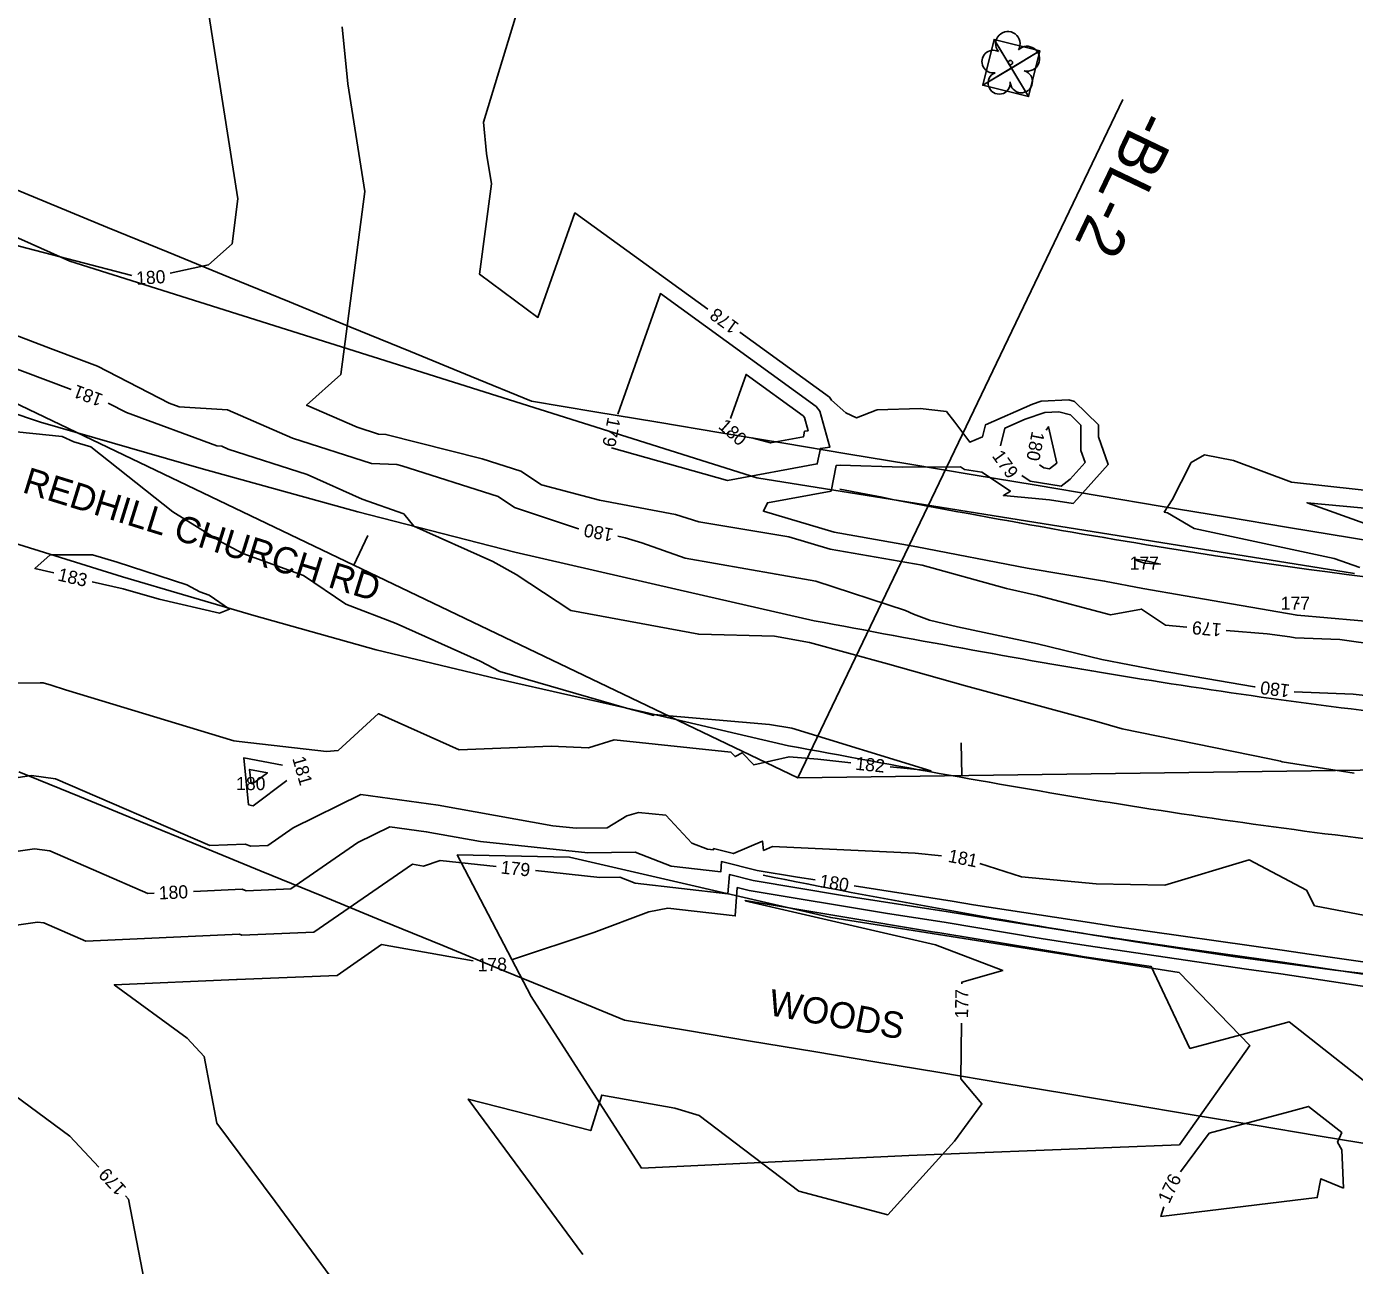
# Model space of a CAD drawing. Extents: x 2086416 to 2115205, y 575507 to 632762.
# Drawn here: x 2110857.5 to 2111059.8, y 581552.3 to 581741 of the extents above; entities that cross this region are included whole.
import ezdxf

# ---------------------------------------------------------------- set-up
doc = ezdxf.new("R2010")
doc.units = 0
for name, color, linetype in [('CTL Bench Mark CELL', 7, 'Continuous'), ('Default', 7, 'Continuous'), ('DTM Contours Major', 7, 'Continuous'), ('DTM Contours Major Text', 7, 'Continuous'), ('DTM Contours Minor', 7, 'Continuous'), ('DTM Contours Minor Text', 7, 'Continuous'), ('Exist Hydrographic FEMA Cross Section', 7, 'Continuous'), ('Exist Right of Way Line', 7, 'Continuous'), ('Exist Roads EOP', 7, 'Continuous'), ('Exist Roads EOP Text', 7, 'Continuous'), ('Exist Vegetation Tree CELL', 7, 'Continuous'), ('Exist Vegetation Woods Line', 7, 'Continuous'), ('Exist Vegetation Woods Line Text', 7, 'Continuous')]:
    doc.layers.add(name, color=color, linetype=linetype)

msp = doc.modelspace()

# ---------------------------------------------------------------- linework, layer by layer
at = {"layer": 'CTL Bench Mark CELL'}
msp.add_line((2111007.5, 581734.68), (2111007.5, 581734.68), dxfattribs=at)
msp.add_lwpolyline([(2111004.87, 581739.03), (2111011.85, 581737.3), (2111010.12, 581730.33), (2111003.15, 581732.05)], close=True, dxfattribs=at)
for points in [[(2111011.85, 581737.3), (2111003.15, 581732.05), (2111007.5, 581734.68), (2111010.12, 581730.33), (2111004.87, 581739.03)], [(2111007.5, 581734.68), (2111011.85, 581737.3), (2111004.87, 581739.03), (2111007.5, 581734.68)], [(2111007.5, 581734.68), (2111003.15, 581732.05), (2111010.12, 581730.33), (2111007.5, 581734.68)]]:
    msp.add_lwpolyline(points, dxfattribs=at)
at = {"layer": 'Default'}
for p, q in [((2110456.37, 581874.95), (2110974.98, 581626.56)), ((2110974.98, 581626.56), (2111024.48, 581729.91)), ((2110907.32, 581658.96), (2110909.48, 581663.47)), ((2110974.98, 581626.56), (2111508.23, 581633.8)), ((2110999.95, 581626.89), (2110999.88, 581631.89))]:
    msp.add_line(p, q, dxfattribs=at)
at = {"layer": 'DTM Contours Major'}
for points in [[(2110857.81, 581782.51), (2110864.26, 581780.86), (2110867.35, 581778.23), (2110871.08, 581774.64), (2110881.14, 581768.63), (2110883.33, 581762.7), (2110885.27, 581742.86), (2110889.69, 581714.76), (2110888.79, 581707.91), (2110885.2, 581704.69), (2110879.38, 581703.43)], [(2110873.53, 581703.08), (2110856.38, 581707.56), (2110842.13, 581711.99), (2110834.59, 581705.91), (2110820.11, 581710.34), (2110817.82, 581710.24), (2110811.38, 581712.14), (2110818.2, 581708.5), (2110833.97, 581702.31), (2110837.45, 581701), (2110842.24, 581699.17)], [(2110847.85, 581697.03), (2110861.11, 581691.96), (2110865.83, 581690.2), (2110868.29, 581689.26), (2110879.23, 581683.6), (2110880.71, 581683.05), (2110888.09, 581682.6), (2110898.02, 581678.3), (2110910.04, 581674.42), (2110913.9, 581674.27), (2110914.63, 581674.08), (2110929.32, 581669.43), (2110931.83, 581667.74), (2110941.39, 581664.51), (2110941.63, 581664.47)], [(2110975.78, 581681.69), (2110967.08, 581688), (2110964.7, 581681.27)], [(2110967.99, 581678.36), (2110970.82, 581677.57), (2110975.83, 581678.48), (2110976.01, 581679.35), (2110976.54, 581679.42), (2110975.97, 581681.44), (2110975.78, 581681.69)], [(2111013.31, 581673.63), (2111014.41, 581674.5), (2111013.16, 581680.03), (2111012.82, 581679.52)], [(2111011.78, 581674.22), (2111012.46, 581673.76), (2111013.31, 581673.63)], [(2110947.53, 581663.35), (2110948.69, 581663.13), (2110951.2, 581662.35), (2110957.79, 581660.03), (2110971.67, 581657.55), (2110977.7, 581656.52), (2110991.39, 581652.02), (2110992.6, 581651.48), (2110995.02, 581650.56), (2110999.28, 581649.57), (2111011.46, 581646.94), (2111021.3, 581644.58), (2111029.72, 581642.96), (2111044.53, 581640.43), (2111044.64, 581640.42)], [(2111050.59, 581639.65), (2111059.56, 581639.3), (2111074.86, 581637.63), (2111092.6, 581635.13), (2111097.3, 581633.95), (2111099.33, 581633.73), (2111122.83, 581631.48), (2111123.23, 581631.44), (2111147.14, 581630.22), (2111147.88, 581630.21), (2111150.02, 581630.22)], [(2110876.9, 581608.98), (2110875.97, 581608.94), (2110861.02, 581615.41), (2110858.67, 581615.72), (2110842.9, 581613.47), (2110829.57, 581614.6), (2110813.49, 581617.62), (2110802.61, 581621.03), (2110784.33, 581624.43), (2110784.33, 581629.17)], [(2110891.68, 581625.67), (2110891.47, 581627.83), (2110894.17, 581627.32), (2110891.91, 581625.62), (2110891.68, 581625.67)], [(2110977.61, 581610.99), (2110974.93, 581611.41), (2110968.79, 581612.43), (2110963.33, 581613.78), (2110963.22, 581612.21), (2110955.69, 581613.08), (2110950.2, 581615.22), (2110942.99, 581615.11), (2110926.63, 581616.85), (2110918.38, 581618.34), (2110912.82, 581619.09), (2110907.96, 581616.69), (2110897.75, 581609.63), (2110890.96, 581609.35), (2110890.33, 581609.58), (2110882.9, 581609.25)], [(2111082.5, 581595.71), (2111075.86, 581596.43), (2111069.63, 581597.3), (2111052.87, 581599.68), (2111049.12, 581600.24), (2111023.26, 581603.91), (2111019.43, 581604.48), (2111001.74, 581607.21), (2110998.51, 581607.75), (2110983.54, 581610.07)]]:
    msp.add_lwpolyline(points, dxfattribs=at)
at = {"layer": 'DTM Contours Minor'}
for points in [[(2110961.28, 581697.94), (2110941.02, 581712.61), (2110935.39, 581696.68), (2110926.5, 581703.26), (2110928.29, 581717.02), (2110927.56, 581721.64), (2110927.09, 581726.43), (2110938.5, 581764.02), (2110958.94, 581787.46), (2110972.43, 581820.41), (2110963.81, 581829.93), (2110966.47, 581833.96)], [(2110905.56, 581740.96), (2110906.42, 581732.25), (2110908.99, 581715.89), (2110905.35, 581687.97), (2110900.14, 581683.3), (2110907.85, 581679.96), (2110911.1, 581678.91), (2110912.22, 581678.87), (2110926.91, 581675.14), (2110932.8, 581673.28), (2110935.94, 581671.16), (2110944.78, 581668.87), (2110956.33, 581666.68), (2110959.91, 581665.57), (2110973.62, 581663.25), (2110979.88, 581661.39), (2110993.91, 581658.93), (2111006.74, 581655.37), (2111011.49, 581654.3), (2111022.59, 581651.38), (2111027.31, 581652.26), (2111030.98, 581649.79), (2111034.24, 581649.51)], [(2110977.78, 581683.12), (2110954.05, 581700.31), (2110947.57, 581681.97)], [(2111033.98, 581654.26), (2111027.52, 581655.4), (2111021.7, 581656.52), (2111009.92, 581658.49), (2110993.12, 581661.76), (2110980.51, 581663.98), (2110969.74, 581667.17), (2110970.33, 581668.46), (2110980.03, 581670.23), (2110980.81, 581674.12), (2110981.43, 581674.2), (2110990.94, 581673.89), (2110999.77, 581673.93), (2111000.38, 581673.54), (2111003, 581673.11), (2111007.37, 581670.24), (2111006.29, 581669.55), (2111013.29, 581668.91), (2111016.9, 581668.36), (2111017.03, 581668.46), (2111022.26, 581674.27), (2111020.76, 581678.49), (2111020.77, 581680.3), (2111017.11, 581683.9), (2111016.28, 581684.11), (2111012.05, 581683.93), (2111010.72, 581683.48), (2111003.55, 581680.3), (2111003.09, 581678.48), (2111001.19, 581677.68), (2110998.91, 581680.74), (2110997.6, 581682.37), (2110993.61, 581682.82), (2110987.06, 581682.61), (2110986.89, 581682.55), (2110983.89, 581681.37), (2110982.3, 581682.15), (2110980.12, 581684.1), (2110979.79, 581684.54), (2110966.14, 581694.42)], [(2110849.4, 581691.27), (2110864.3, 581685.71)], [(2110869.92, 581683.61), (2110870.01, 581683.58), (2110872.69, 581682.19), (2110886.48, 581677.11), (2110887.21, 581677.07), (2110888.2, 581676.64), (2110900.23, 581672.75), (2110908.61, 581668.98), (2110914.95, 581666.77), (2110916.46, 581664.89), (2110928.52, 581659.48), (2110932.08, 581657.5), (2110940.41, 581652.05), (2110959.88, 581648.42), (2110971.42, 581648.11), (2110976.77, 581647.17), (2110988.63, 581643.91), (2111000.53, 581640.56), (2111020.53, 581635.11), (2111024.4, 581634.03), (2111046.82, 581629.45), (2111048.5, 581629.07), (2111048.77, 581629), (2111059.73, 581627.25)], [(2110946.57, 581676.83), (2110964.27, 581671.86), (2110977.93, 581674.36), (2110978.41, 581676.74), (2110979.85, 581676.92), (2110978.32, 581682.42), (2110977.78, 581683.12)], [(2111018.07, 581676.4), (2111018.1, 581680.27), (2111016.5, 581681.84), (2111014.71, 581682.29), (2111012.62, 581682.2), (2111009.6, 581681.2), (2111006.53, 581679.83), (2111005.84, 581677.12)], [(2110842.52, 581680.61), (2110862.89, 581678.56), (2110864.67, 581677.73), (2110867.29, 581676.98), (2110879.75, 581667.09), (2110887.27, 581662.38), (2110890.41, 581660.71), (2110899.69, 581657.39), (2110906.1, 581653), (2110913.79, 581650.08), (2110926.59, 581644.34), (2110929.58, 581642.73), (2110948.86, 581637.16), (2110951.39, 581636.51), (2110953.03, 581636.04), (2110953.05, 581636.21), (2110970.66, 581634.65), (2110974.07, 581634.09), (2110995.24, 581627.6), (2110989.03, 581628.23)], [(2111009.08, 581672.6), (2111010.38, 581671.72), (2111015.11, 581671), (2111016.46, 581672.07), (2111018.72, 581674.58), (2111018.07, 581676.4)], [(2111076.02, 581668.76), (2111050.2, 581671.6), (2111041.35, 581674.9), (2111036.91, 581675.75), (2111034.88, 581674.58), (2111033.37, 581671.6), (2111032.02, 581668.91), (2111030.8, 581667.04), (2111031.29, 581666.94), (2111035.33, 581664.54), (2111056.7, 581659.98), (2111060.58, 581658.59)], [(2111070.83, 581661.91), (2111052.56, 581668.44), (2111077.82, 581666.09), (2111082.45, 581665.57)], [(2110885.29, 581654.39), (2110883.87, 581654.9), (2110881.88, 581655.95), (2110871.29, 581659.4), (2110867.53, 581660.53), (2110861.07, 581660.53), (2110858.75, 581658.42), (2110861.64, 581657.76)], [(2111027.79, 581659.26), (2111026.7, 581659.61), (2111026.31, 581659.85), (2111027.78, 581659.67), (2111027.84, 581659.66), (2111030.19, 581659.12), (2111027.79, 581659.26)], [(2110867.49, 581656.41), (2110872.18, 581655.33), (2110877.68, 581653.75), (2110886.89, 581651.63), (2110888.4, 581652.26), (2110885.29, 581654.39)], [(2111168.17, 581645.41), (2111168.97, 581645.31), (2111172.74, 581644.84), (2111194.02, 581644.23), (2111176.11, 581643.9), (2111172.57, 581643.81), (2111158.61, 581644.07), (2111154.65, 581644.18), (2111135.04, 581644.56), (2111124.61, 581644.89), (2111115.46, 581645.42), (2111106.17, 581646.37), (2111094.09, 581647.15), (2111076.28, 581648.94), (2111064.89, 581650.09), (2111051.02, 581651.31), (2111033.98, 581654.26)], [(2111050.81, 581653.14), (2111051.17, 581653.11), (2111051.34, 581653.08), (2111051.31, 581653.07), (2111051.18, 581653.08), (2111051.14, 581653.08), (2111050.81, 581653.14)], [(2111040.21, 581649), (2111046.47, 581648.46), (2111049.91, 581648.03), (2111050.75, 581647.88), (2111057.54, 581647.61), (2111075.81, 581645.03), (2111083.62, 581643.07), (2111103.56, 581640.9), (2111112.25, 581640.07), (2111123.96, 581638.8), (2111133.06, 581638.34), (2111152.19, 581638), (2111160.29, 581638.04), (2111171.77, 581637.82), (2111172.14, 581637.73), (2111178.61, 581637.94), (2111201.19, 581638.98), (2111205.15, 581639.2), (2111206.66, 581639.57), (2111221.28, 581640.1), (2111223.41, 581640.06), (2111239.38, 581640.48)], [(2110983.07, 581628.85), (2110978, 581629.37), (2110973.65, 581629.75), (2110968.25, 581628.5), (2110966.51, 581630.36), (2110965.42, 581629.78), (2110964.79, 581630.46), (2110947.02, 581632.32), (2110943.07, 581631.1), (2110937.41, 581631.35), (2110923.38, 581630.81), (2110911.16, 581636.31), (2110911.1, 581636.32), (2110904.94, 581630.73), (2110903.18, 581630.56), (2110889.88, 581632.09), (2110889.08, 581632.18), (2110863.41, 581639.97), (2110861.22, 581640.65), (2110861.21, 581640.65), (2110860.03, 581641), (2110859.55, 581641.04), (2110830.03, 581640.99)], [(2110929.04, 581613.04), (2110920.49, 581613.95), (2110917.95, 581613.11), (2110916.27, 581613.41), (2110901.27, 581603.04), (2110890.27, 581602.57), (2110889.9, 581602.71), (2110866.52, 581601.67), (2110860.13, 581604.43), (2110859.13, 581604.56), (2110830.62, 581600.5), (2110829.64, 581600.58), (2110804.08, 581605.37), (2110803.32, 581605.61), (2110774.57, 581610.97), (2110774.57, 581632.28), (2110758.83, 581634.4), (2110756.92, 581632.1)], [(2110891.27, 581622.44), (2110890.57, 581629.59), (2110896.48, 581628.48)], [(2110753.08, 581627.49), (2110744.05, 581616.65), (2110743.92, 581616.36), (2110723.28, 581627.9), (2110743.8, 581615.32), (2110744.35, 581615.09), (2110773.2, 581609.58), (2110773.78, 581609.34), (2110774.18, 581609.1), (2110802.91, 581603.58), (2110803.77, 581602.94), (2110829.06, 581598.07), (2110829.72, 581597.73), (2110848.6, 581586.56), (2110853.13, 581580), (2110864.1, 581571.94), (2110868.48, 581567.23)], [(2110996.86, 581614.66), (2110992.83, 581615.07), (2110971.13, 581616.07), (2110969.76, 581615.48), (2110969.59, 581616.9), (2110965.17, 581615), (2110962.13, 581615.76), (2110962.11, 581615.56), (2110961.19, 581615.67), (2110958.82, 581616.6), (2110954.89, 581620.84), (2110950.68, 581621.28), (2110948.91, 581620.73), (2110945.91, 581618.94), (2110941.19, 581618.86), (2110937.67, 581619.24), (2110920.18, 581622.39), (2110908.4, 581623.98), (2110898.09, 581618.9), (2110894.23, 581616.23), (2110891.66, 581616.12), (2110890.77, 581616.45), (2110885.42, 581616.21), (2110861.9, 581626.39), (2110858.22, 581626.88), (2110855.17, 581626.45)], [(2110897.15, 581626.15), (2110892.02, 581622.27), (2110891.27, 581622.44)], [(2111196.72, 581603.77), (2111172.9, 581599.04), (2111171.11, 581598.89), (2111169.44, 581598.86), (2111145.84, 581603.49), (2111139.11, 581602.96), (2111128.42, 581602.29), (2111121.08, 581599.17), (2111117.24, 581599.62), (2111101.55, 581602.41), (2111089.76, 581603.22), (2111073.51, 581605.15), (2111070.03, 581604.02), (2111065.65, 581604.74), (2111053.68, 581607.05), (2111052.47, 581609.42), (2111043.72, 581614.04), (2111030.87, 581610.21), (2111020.41, 581610.41), (2111009.04, 581611.48), (2111002.71, 581613.49)], [(2111130.22, 581588.38), (2111121.05, 581588.76), (2111106.61, 581590.81), (2111099.14, 581591.63), (2111088.39, 581592.8), (2111069.38, 581595.44), (2111061.09, 581596.62), (2111048.83, 581598.45), (2111033.29, 581600.66), (2111019.16, 581602.75), (2111006.9, 581604.64), (2110997.88, 581606.14), (2110981.78, 581608.64), (2110968.18, 581610.9), (2110964.54, 581611.8), (2110964.32, 581608.85), (2110950.19, 581610.5), (2110947.86, 581611.4), (2110944.79, 581611.36), (2110935.01, 581612.4)], [(2111089.4, 581555.52), (2111077.55, 581561.12), (2111076.79, 581568.08), (2111074.63, 581570.74), (2111076.73, 581572.4), (2111068.24, 581581.12), (2111061.92, 581586.55), (2111068.35, 581593.7), (2111048.53, 581596.67), (2111043.32, 581597.41), (2111018.89, 581601.02), (2111012.06, 581602.08), (2110997.25, 581604.54), (2110988.64, 581605.87), (2110967.58, 581609.38), (2110965.75, 581609.83), (2110965.43, 581605.5), (2110955.18, 581606.69), (2110952.29, 581606.13), (2110943.89, 581602.96), (2110931.34, 581598.81)], [(2111061.52, 581539.99), (2111063.18, 581540.25), (2111064.17, 581540.37), (2111066.23, 581550.97), (2111066.29, 581550.94), (2111065.54, 581568.97), (2111063.51, 581572.55), (2111065.42, 581577.09), (2111049.84, 581589.37), (2111048.92, 581589.13), (2111034.71, 581585.33), (2111028.8, 581597.79), (2111018.62, 581599.29), (2111017.22, 581599.51), (2110996.62, 581602.93), (2110995.49, 581603.1), (2110966.97, 581607.85), (2110966.96, 581607.85), (2110966.96, 581607.82), (2110967.56, 581607.66), (2110995.97, 581601.12), (2111006.18, 581597.21), (2110999.98, 581595.42), (2110999.97, 581595.17)], [(2110925.52, 581598.64), (2110911.57, 581601.13), (2110904.79, 581596.44), (2110889.57, 581595.8), (2110889.46, 581595.84), (2110870.84, 581595.01), (2110881.93, 581586.86), (2110884.54, 581584.07), (2110886.49, 581573.95), (2110895.38, 581561.98), (2110911.97, 581539.46)], [(2110999.9, 581589.17), (2110999.8, 581580.68), (2111003.02, 581576.87), (2110998.83, 581571.21), (2110988.66, 581559.99), (2110975.14, 581563.57), (2110959.96, 581575.11), (2110956.22, 581576.23), (2110945.1, 581578.22), (2110943.43, 581572.79), (2110924.77, 581577.6), (2110942.21, 581553.94)], [(2111058.1, 581564.04), (2111057.86, 581569.87), (2111057.2, 581571.02), (2111057.82, 581572.49), (2111052.78, 581576.47), (2111049.99, 581575.72), (2111037.65, 581572.42), (2111033.27, 581566.52)], [(2111030.73, 581561.17), (2111030.28, 581559.69), (2111054.1, 581562.6), (2111054.65, 581565.45), (2111058.1, 581564.04)], [(2110872.57, 581562.84), (2110873.01, 581562.37), (2110879.72, 581527.7), (2110880.43, 581526.75), (2110881.74, 581524.97)]]:
    msp.add_lwpolyline(points, dxfattribs=at)
at = {"layer": 'Exist Hydrographic FEMA Cross Section'}
for points in [[(2111068.93, 581661.5), (2111059.32, 581663.1), (2111049.71, 581664.7), (2111040.1, 581666.3), (2111030.49, 581667.9), (2111020.89, 581669.5), (2111011.28, 581671.11), (2111001.67, 581672.71), (2110992.06, 581674.31), (2110982.45, 581675.91), (2110972.85, 581677.51), (2110963.24, 581679.11), (2110953.63, 581680.71), (2110944.03, 581682.32), (2110934.42, 581683.91), (2110925.19, 581687.7), (2110915.97, 581691.48), (2110906.74, 581695.27), (2110897.52, 581699.06), (2110888.29, 581702.84), (2110879.07, 581706.62), (2110869.84, 581710.41), (2110860.61, 581714.19), (2110851.39, 581717.98)], [(2111063.86, 581570.42), (2111054.26, 581572.02), (2111044.65, 581573.62), (2111035.04, 581575.22), (2111025.43, 581576.83), (2111015.82, 581578.43), (2111006.21, 581580.02), (2110996.6, 581581.63), (2110987, 581583.23), (2110977.39, 581584.83), (2110967.78, 581586.43), (2110958.18, 581588.03), (2110948.57, 581589.63), (2110939.34, 581593.42), (2110930.11, 581597.2), (2110920.89, 581600.99), (2110911.67, 581604.77), (2110902.44, 581608.56), (2110893.22, 581612.34), (2110883.99, 581616.13), (2110874.77, 581619.91), (2110865.54, 581623.7), (2110856.32, 581627.48)]]:
    msp.add_lwpolyline(points, dxfattribs=at)
at = {"layer": 'Exist Right of Way Line'}
for centre, radius, start, end in [((2111262.84, 583087.65), 1444.79, 258.76631, 260.84314), ((2111174.98, 582542.55), 892.65, 260.84314, 266.74835), ((2111262.84, 583087.65), 1504.79, 258.76631, 260.84314), ((2111174.98, 582542.55), 952.65, 260.84314, 266.74835)]:
    msp.add_arc(centre, radius, start, end, dxfattribs=at)
at = {"layer": 'Exist Roads EOP'}
for points in [[(2110859.62, 581680.71), (2110839.18, 581687.57), (2110822.39, 581693.78), (2110804.41, 581700.49), (2110791.36, 581705.43), (2110777.14, 581711.28), (2110760, 581718.68), (2110741.24, 581726.89), (2110721.85, 581735.85), (2110702.22, 581745.1), (2110680.73, 581755.98), (2110662.27, 581765.85)], [(2110661.71, 581744.29), (2110681.63, 581733.96), (2110708.85, 581721.01), (2110734.15, 581708.98), (2110768.01, 581694.36), (2110797.99, 581682.47), (2110825.02, 581672.22), (2110850.72, 581663.8), (2110872.12, 581657.17), (2110892.09, 581651.25), (2110910.76, 581646.06), (2110929.15, 581641.61), (2110951.61, 581636.54), (2110973.54, 581631.44)], [(2110977.48, 581650.48), (2110956.38, 581655.31), (2110931.86, 581660.94), (2110907.94, 581667.06), (2110884.07, 581673.67), (2110859.62, 581680.71)]]:
    msp.add_lwpolyline(points, dxfattribs=at)
for points in [[(2110977.48, 581650.48), (2111025.79, 581641.84), (2111074.55, 581635.25), (2111123.2, 581631.18), (2111172.22, 581629.18), (2111221.29, 581629.52), (2111270.17, 581631.7), (2111319.13, 581635.84), (2111368.33, 581641.12), (2111417.78, 581647.42)], [(2110973.54, 581631.44), (2111022.55, 581622.76), (2111072.45, 581615.95), (2111122.07, 581611.59), (2111171.98, 581610.01), (2111221.99, 581610.11), (2111271.48, 581612.54), (2111320.96, 581616.67), (2111370.32, 581622.18), (2111419.52, 581628.55)]]:
    msp.add_spline(points, degree=3, dxfattribs=at)
at = {"layer": 'Exist Vegetation Tree CELL'}
msp.add_line((2111007.35, 581735.51), (2111007.35, 581735.51), dxfattribs=at)
msp.add_circle((2111007.35, 581735.51), 0.326, dxfattribs=at)
for centre, radius, start, end in [((2111006.97, 581738.39), 1.86, 330.1651, 219.7134), ((2111004.75, 581735.67), 1.73, 62.6636, 279.3457), ((2111009.9, 581736.1), 1.9, 257.1011, 134.1999), ((2111005.65, 581732.39), 1.69, 111.5671, 6.231), ((2111009.02, 581732.61), 1.7, 181.2822, 74.56)]:
    msp.add_arc(centre, radius, start, end, dxfattribs=at)
at = {"layer": 'Exist Vegetation Woods Line'}
for points in [[(2111059.79, 581657.65), (2110968.73, 581672.25), (2110864.06, 581705.25), (2110784.73, 581740.8), (2110702.3, 581784.67), (2110632.54, 581823.34), (2110568.48, 581865.95), (2110498.27, 581913.79), (2110441.66, 581966.78), (2110387.94, 582016.39), (2110334.43, 582063.69), (2110284.48, 582120.87)], [(2111033.08, 581596.9), (2111043.81, 581585.75), (2111033.1, 581570.65), (2110991.9, 581569.03), (2110951.17, 581567.08), (2110934.36, 581593.21), (2110923.1, 581614.81), (2110940.19, 581614.48)], [(2110940.19, 581614.48), (2110979.98, 581605.26), (2111033.08, 581596.9)]]:
    msp.add_lwpolyline(points, dxfattribs=at)

# ---------------------------------------------------------------- texts
at = {"layer": 'Default'}
msp.add_text('-BL-2', height=7, rotation=244.407, dxfattribs=at).set_placement((2111026.92, 581728.74))
at = {"layer": 'DTM Contours Major Text'}
for rotation, p in [(3.366, (2110874.24, 581701.66)), (318.4729, (2110962.73, 581679.93)), (258.9078, (2111010.63, 581679.44)), (169.2205, (2110947, 581664.46)), (172.687, (2111050, 581640.74)), (351.1764, (2110978.17, 581609.89)), (2.5491, (2110877.67, 581608.01))]:
    msp.add_text('180', height=2, rotation=rotation, dxfattribs=at).set_placement(p)
msp.add_text('180', height=2, dxfattribs=at).set_placement((2110889.41, 581624.67))
at = {"layer": 'DTM Contours Minor Text'}
for s, rotation, p in [('178', 144.084, (2110966.14, 581695.65)), ('181', 159.5025, (2110869.28, 581684.92)), ('179', 258.9249, (2110946.03, 581681.57)), ('179', 305.664, (2111004.47, 581675.57)), ('183', 347.0316, (2110862.12, 581656.62)), ('179', 175.0859, (2111039.58, 581650.05)), ('181', 285.976, (2110897.94, 581629.51)), ('182', 354.1396, (2110983.68, 581627.78)), ('181', 348.7424, (2110997.75, 581613.75)), ('179', 353.9173, (2110929.65, 581611.97)), ('178', 1.661, (2110926.23, 581597.04)), ('177', 89.2978, (2111000.91, 581589.88)), ('179', 132.9468, (2110872.81, 581564.05)), ('176', 64.5646, (2111031.54, 581561.56))]:
    msp.add_text(s, height=2, rotation=rotation, dxfattribs=at).set_placement(p)
for p in [(2111025.52, 581658.26), (2111048.53, 581652.14)]:
    msp.add_text('177', height=2, dxfattribs=at).set_placement(p)
at = {"layer": 'Exist Roads EOP Text'}
msp.add_text('TO REDHILL CHURCH RD', height=4, rotation=342.7594, dxfattribs=at).set_placement((2110848.16, 581672.74))
at = {"layer": 'Exist Vegetation Woods Line Text'}
msp.add_text('WOODS', height=4, rotation=349.5682, dxfattribs=at).set_placement((2110970.32, 581590.44))

doc.saveas('drawing.dxf')
